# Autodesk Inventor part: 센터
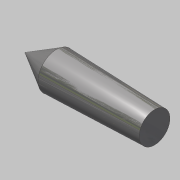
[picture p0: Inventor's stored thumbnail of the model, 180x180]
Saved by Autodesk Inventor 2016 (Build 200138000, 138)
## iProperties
Created: 2019-10
Part Number: 센터
Material: 스테인리스강
Document SubType Name: Modeling
Designer: mduedu
Density: 1 g/cm^3
Appearance: 반광택
Author: mduedu
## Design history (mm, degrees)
sketch "스케치1"
  geometry: L1 (0, 0)-(-31.5, 0); L2 (-31.5, 0)-(-31.5, -0.125); L3 (-31.5, -0.125)-(-23.922, -4.5); L4 (-23.922, -4.5)-(0, -3.751); L5 (0, -3.751)-(0, 0)
  constraints: 10 end point, 1 horizontal, 1 parallel, 1 perpendicular
  dimensions: "d0" = 31.5 distance of L1.start L1.end; "d1" = 7.502 diameter of L4.end L1; "d2" = 30 deg angle of L1 L3; "d3" = 7.578 horizontal distance of L2.end L3.end; "d5" = 0.25 diameter of L2.end L1; "d6" = 23.922 horizontal distance of L3.end L4.end (derived); "d7" = 9.00032 diameter of L3.end L1 (derived)
revolve "회전1" sketch "스케치1" stored, may be unused: angle "d8" = 90 deg
node "솔리드1"
